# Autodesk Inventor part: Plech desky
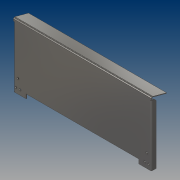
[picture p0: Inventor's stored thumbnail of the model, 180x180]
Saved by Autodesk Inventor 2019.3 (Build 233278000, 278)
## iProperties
Created: 2019-02
Part Number: Plech desky
Material: Nerezová ocel
Document SubType Name: Plech
Designer: B-hon
Density: 8 g/cm^3
Sheet Metal Rule: Výchozí_mm
Appearance: Ocel – leštěná
Author: B-hon
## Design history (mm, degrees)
node "Plocha1"
  sketch "Náčrt1"
    geometry: L1 (65, 0)-(643, 0) reference; L2 (708, 281)-(0, 281); L3 (65, 0)-(65, -45); L4 (65, -45)-(0, -45) reference; L5 (708, -45)-(643, -45) reference; L6 (643, -45)-(643, 0); L7 (0, 281)-(0, -45); L8 (708, 281)-(708, -45); 2 further points
    constraints: 16 end point, 4 horizontal, 2 vertical, 1 midpoint, 1 parallel, 1 other
    dimensions: "d1" = 281 distance of L2.end point (0, 0); "d137" = 708 distance of L2.start L2.end; "d138" = 65 distance of L3.end L4.end; "d139" = 65 distance of L5.start L5.end
node "Upravit přímo1"
node "Obruba2"
node "Obruba3"
sketch "Náčrt13"
  geometry: L1 (0, -45)-(0, 281) reference; L2 (6, 32.758)-(41, 32.758); L3 (41, 32.758)-(41, -27.242); L4 (41, -27.242)-(6, -27.242); L5 (6, -27.242)-(6, 32.758); L6 (6, 281)-(702, 281) reference; L7 (65, -45)-(6, -45) reference; 4 further points
  constraints: 8 end point, 2 parallel, 1 horizontal, 1 horizontal alignment, 1 perpendicular
  dimensions: "d141" = 41 distance between parallel lines of L3 L1; "d142" = 35 distance of L2.start L2.end; "d143" = 60 distance of L2.end L3.end; "d144" = 21 distance of point (34, -20.242) point (13, -20.242); "d145" = 10.5 horizontal distance of point (13, -20.242) point (23.5, 24.758) (= 0.5 x d144); "d146" = 45 vertical distance of point (13, -20.242) point (23.5, 24.758); "d147" = 7 distance from line of L4 point (13, -20.242); "d148" = 13 distance from line of L1 point (13, -20.242); "d181" = 69.75832 distance from line of L7 point (23.5, 24.758)
hole "Díra7" sketch "Náčrt13" at (13, -20.242), (34, -20.242), (23.5, 24.758) diameter "d149" = 5.5; stored, may be unused: countersink angle "d153" = 90 deg, drill point angle "d155" = 118 deg; dims "d150" = 10, "d151" = 10.5, "d152" = 2, "d154" = 3 (= Tloušťka)
pattern_linear "Obdélníkové pole7" dims "d158" = 661
node "Upravit přímo2"
node "Upravit přímo4"
sketch "Náčrt14"
  geometry: L1 (696, 0)-(0, 0) reference; L2 (0, -3)-(696, -3) reference; L3 (0, -3)-(0, 0) reference; L4 (696, -3)-(696, 0) reference; 1 further point
extrude "Vysunutí2" join sketch "Náčrt14" distance "d191" = 1; taper "d192" = 0 deg
sketch "Náčrt15"
  geometry: L1 (-6, -3)-(702, -3); L2 (702, -3)-(702, 0); L3 (702, 0)-(-6, 0); L4 (-6, 0)-(-6, -3); 5 further points
  constraints: 8 end point, 4 point on line, 2 parallel, 1 horizontal, 1 perpendicular
extrude "Vysunutí3" join sketch "Náčrt15" distance "d193" = 10; taper "d194" = 0 deg
node "Obruba4"
chamfer "Zkosení7" distance "d205" = 10; stored, may be unused: second distance "d206" = 2, angle "d207" = 15 deg
node "Těleso1"
feature "Deska1" dims "d8" = 3 (= Tloušťka)
sketch "Náčrt10"
  geometry: L1 through (163, 0) direction (-1, 0); L2 through (0, -12.5) direction (0, -1); L3 (0, -25)-(326, -25); L4 (326, -25)-(326, 0)
  constraints: 6 end point, 1 horizontal, 1 perpendicular, 1 vertical
feature "Deska3" dims "d8" = 3 (= Tloušťka), "d106" = 3 (= ŠířkaVýštipu), "d107" = 1.5 (= HloubkaVýštipu), "d108" = 6 (= MinimálníZbytek), "d109" = 3 (= PřechodovýPoloměr), "d110" = 25, "d111" = 90 deg, "d112" = 3 (= PoloměrOhybu), "d113" = 12 (= VelikostRohovéhoVýštipu), "d114" = 3 (= VelikostMezery), "d115" = 3 (= VelikostJacobihoPoloměru), "MezeraVystřižení" = 0.01
feature "Ohyb2" dims "d8" = 3 (= Tloušťka), "d106" = 3 (= ŠířkaVýštipu), "d107" = 1.5 (= HloubkaVýštipu), "d108" = 6 (= MinimálníZbytek), "d109" = 3 (= PřechodovýPoloměr), "d110" = 25, "d111" = 90 deg, "d112" = 3 (= PoloměrOhybu), "MezeraVystřižení" = 0.01
feature "Roh2" dims "d110" = 25, "d111" = 90 deg, "d113" = 12 (= VelikostRohovéhoVýštipu), "d114" = 3 (= VelikostMezery), "d115" = 3 (= VelikostJacobihoPoloměru)
sketch "Náčrt11"
  geometry: L1 through (163, 0) direction (-1, -8.37e-36); L2 through (0, -12.5) direction (-8.38e-33, -1); L3 (0, -25)-(326, -25); L4 (326, -25)-(326, 0)
  constraints: 6 end point, 1 horizontal, 1 perpendicular, 1 vertical
feature "Deska4" dims "d8" = 3 (= Tloušťka), "d116" = 3 (= ŠířkaVýštipu), "d117" = 1.5 (= HloubkaVýštipu), "d118" = 6 (= MinimálníZbytek), "d119" = 3 (= PřechodovýPoloměr), "d120" = 25, "d121" = 90 deg, "d122" = 3 (= PoloměrOhybu), "d123" = 12 (= VelikostRohovéhoVýštipu), "d124" = 3 (= VelikostMezery), "d125" = 3 (= VelikostJacobihoPoloměru), "MezeraVystřižení" = 0.01
feature "Ohyb3" dims "d8" = 3 (= Tloušťka), "d116" = 3 (= ŠířkaVýštipu), "d117" = 1.5 (= HloubkaVýštipu), "d118" = 6 (= MinimálníZbytek), "d119" = 3 (= PřechodovýPoloměr), "d120" = 25, "d121" = 90 deg, "d122" = 3 (= PoloměrOhybu), "MezeraVystřižení" = 0.01
feature "Roh3" dims "d120" = 25, "d121" = 90 deg, "d123" = 12 (= VelikostRohovéhoVýštipu), "d124" = 3 (= VelikostMezery), "d125" = 3 (= VelikostJacobihoPoloměru)
sketch "Náčrt16"
  geometry: L1 through (354, 0) direction (-1, -1.59e-16); L2 through (0, -36.09) direction (4.13e-17, -1); L3 (0, -72.181)-(708, -72.181); L4 (708, -72.181)-(708, 0)
  constraints: 6 end point, 1 horizontal, 1 perpendicular, 1 vertical
feature "Deska5" dims "d8" = 3 (= Tloušťka), "d195" = 3 (= ŠířkaVýštipu), "d196" = 1.5 (= HloubkaVýštipu), "d197" = 6 (= MinimálníZbytek), "d198" = 3 (= PřechodovýPoloměr), "d199" = 80, "d200" = 105 deg, "d201" = 3 (= PoloměrOhybu), "d202" = 12 (= VelikostRohovéhoVýštipu), "d203" = 3 (= VelikostMezery), "d204" = 3 (= VelikostJacobihoPoloměru), "MezeraVystřižení" = 0.01
feature "Ohyb4" dims "d8" = 3 (= Tloušťka), "d195" = 3 (= ŠířkaVýštipu), "d196" = 1.5 (= HloubkaVýštipu), "d197" = 6 (= MinimálníZbytek), "d198" = 3 (= PřechodovýPoloměr), "d199" = 80, "d200" = 105 deg, "d201" = 3 (= PoloměrOhybu), "MezeraVystřižení" = 0.01
feature "Roh4" dims "d199" = 80, "d200" = 105 deg, "d202" = 12 (= VelikostRohovéhoVýštipu), "d203" = 3 (= VelikostMezery), "d204" = 3 (= VelikostJacobihoPoloměru)
feature "Posunout1" dims "d56" = 23
feature "Posunout2" dims "d167" = -2
feature "Posunout3" dims "d170" = -2
feature "Posunout5" dims "d190" = -10
other parameters: "Tloušťka" = 3 (derived), "KSoučinitel" = 4.4, "PoloměrOhybu" = 3 (= Tloušťka), "ŠířkaVýštipu" = 3 (= Tloušťka), "HloubkaVýštipu" = 1.5 (= 0.5 x Tloušťka), "VelikostRohovéhoVýštipu" = 12 (= 4 x Tloušťka), "MinimálníZbytek" = 6 (= 2 x Tloušťka), "PřechodovýPoloměr" = 3 (= PoloměrOhybu), "VelikostJacobihoPoloměru" = 3 (= PoloměrOhybu), "VelikostMezery" = 3 (= Tloušťka), "d54" = 0, "d55" = 0, "d165" = 0, "d166" = 0, "d168" = 0, "d169" = 0, "d188" = 0, "d189" = 0
